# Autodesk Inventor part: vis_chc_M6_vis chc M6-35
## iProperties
Shininess: 64.0
Length Units: 11269
Angle Units: 11279
Time Units: 11290
Mass Units: 11283
Length Display Precision: 3
Angle Display Precision: 2
Compacted: True
Part Number: vis_chc_M6_vis chc M6-35
Document SubType Name: Modeling
Created: 2006-01
Material: Par défaut
Designer: riri
Density: 0.0
Volumn: 0.0
Area: 0.0
PropertySet Name: Model Information
Control State: 0
Master: False
Checked Out: False
Author: riri
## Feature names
1. Base1
